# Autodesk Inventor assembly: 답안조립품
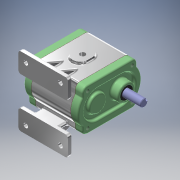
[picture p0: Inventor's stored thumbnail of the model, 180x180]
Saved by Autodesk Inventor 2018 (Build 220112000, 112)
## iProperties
Created: 2023-06
Part Number: 답안조립품
Material: 일반
Document SubType Name: Assembly
Designer: home
Author: home
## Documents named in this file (11)
- C:\Users\home\Desktop\730606V1014\답안조립품.iam
- C:\Users\home\Desktop\730606V1014\본체.ipt
- C:\Users\home\Desktop\730606V1014\뒷커버.ipt
- C:\Users\home\Desktop\730606V1014\가스켓.ipt
- C:\Users\home\Desktop\730606V1014\앞커버.ipt
- C:\Users\home\Desktop\730606V1014\오일실 15 25 7.ipt
- C:\Users\home\Desktop\730606V1014\니들베어링 NA 4902.ipt
- C:\Users\home\Desktop\730606V1014\서브 드라이브 기어.ipt
- C:\Users\home\Desktop\730606V1014\메인 드라이브 기어.ipt
- C:\Users\home\Desktop\730606V1014\샤프트.ipt
- C:\Users\home\Desktop\730606V1014\묻힘키 6x6x40.ipt
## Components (2 placed, 1 different names)
1. 가스켓:1
2. 가스켓:2
